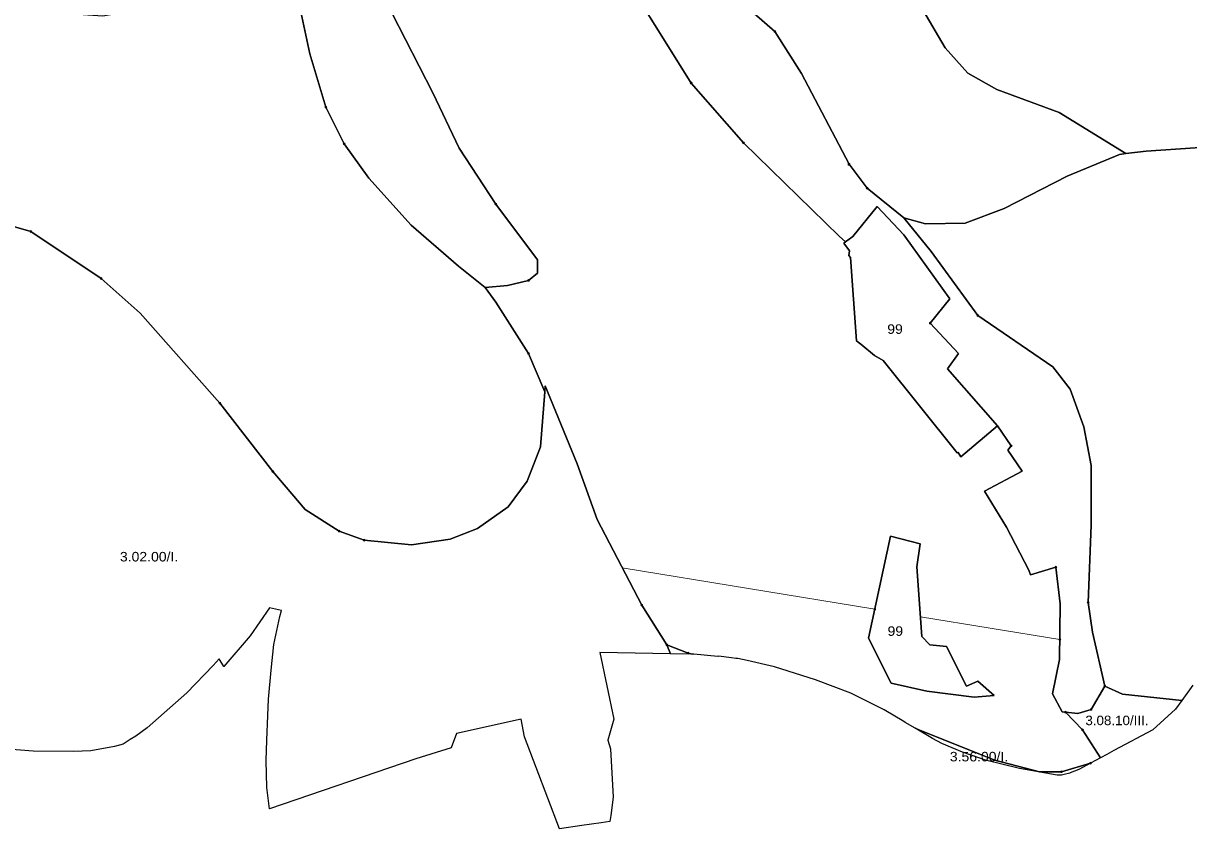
# Model space of a CAD drawing. Extents: x -650455 to -642254, y -1075222 to -1066610.
# Drawn here: x -646878 to -645652, y -1073104 to -1072257 of the extents above; entities that cross this region are included whole.
import ezdxf
from ezdxf.enums import TextEntityAlignment as Align

# ---------------------------------------------------------------- set-up
doc = ezdxf.new("R2010")
doc.units = 0
doc.header["$LTSCALE"] = 4
doc.header["$PDMODE"] = 32
doc.header["$PDSIZE"] = 2
for name, color, linetype, lineweight in [('1', 7, 'Continuous', 25), ('11', 7, 'Continuous', 13), ('13', 7, 'Continuous', 13), ('14', 7, 'Continuous', 13)]:
    doc.layers.add(name, color=color, linetype=linetype, lineweight=lineweight)
doc.layers.add('2', color=7, linetype='Continuous')

msp = doc.modelspace()

# ---------------------------------------------------------------- linework, layer by layer
at = {"layer": '1'}
for points in [[(-646550.686, -1071915.879), (-646559.5, -1071929.501), (-646506, -1071973.001), (-646478, -1071996), (-646472.545, -1072000), (-646448, -1072018.001), (-646420, -1072041), (-646408.5, -1072055.501), (-646389.5, -1072061.5), (-646345.4, -1072092.965), (-646345, -1072092.5), (-646296, -1072139.001), (-646248.5, -1072203), (-646175.5, -1072320), (-646120.5, -1072383.001), (-646020, -1072481), (-646013.29, -1072487.101)], [(-646908.5, -1072213.001), (-646859, -1072238.5), (-646830.5, -1072247), (-646794, -1072249.501), (-646766, -1072244.501), (-646725, -1072227.5), (-646651, -1072186), (-646624, -1072184.001), (-646611, -1072194), (-646595.5, -1072213.001), (-646588, -1072235.5), (-646576.5, -1072289.501), (-646559.5, -1072345.501), (-646540.5, -1072384), (-646514.5, -1072420.001), (-646470, -1072469.5), (-646420, -1072512.501), (-646392, -1072535), (-646381, -1072550.5), (-646346.5, -1072604.501), (-646329.469, -1072644.503), (-646334, -1072702.501), (-646348, -1072738.501), (-646368, -1072765.5)], [(-645894.5, -1072604.501), (-645924, -1072572.501), (-645903.5, -1072547), (-645952, -1072479.501), (-645979.711, -1072449.972), (-646005.6, -1072481.541), (-646013.29, -1072487.101), (-646020, -1072481), (-646120.5, -1072383.001), (-646175.5, -1072320), (-646248.5, -1072203)], [(-646504.5, -1072218), (-646447, -1072330.501), (-646419.5, -1072388.5), (-646381, -1072447.501), (-646337, -1072506), (-646337, -1072520.001), (-646346.5, -1072527.501), (-646368.5, -1072533.001), (-646392, -1072535), (-646420, -1072512.501), (-646470, -1072469.5), (-646514.5, -1072420.001), (-646540.5, -1072384), (-646559.5, -1072345.501), (-646576.5, -1072289.501), (-646588, -1072235.5)], [(-646044.852, -1072947.399), (-646087.992, -1072933.791), (-646116.558, -1072926.987), (-646126.295, -1072925.154), (-646128.552, -1072925.154), (-646133.068, -1072924.166), (-646146.615, -1072922.613), (-646147.305, -1072922.889), (-646172.567, -1072920.556), (-646174.324, -1072920.525), (-646178.5, -1072919.5), (-646201, -1072910.5), (-646227.5, -1072869.001), (-646274.5, -1072779.001), (-646295.5, -1072720.5), (-646329, -1072638.501), (-646329.469, -1072644.503), (-646346.5, -1072604.501), (-646381, -1072550.5), (-646392, -1072535), (-646368.5, -1072533.001), (-646346.5, -1072527.501), (-646337, -1072520.001), (-646337, -1072506), (-646381, -1072447.501), (-646419.5, -1072388.5), (-646447, -1072330.501), (-646504.5, -1072218)], [(-645932, -1072243), (-645908.5, -1072283), (-645884.5, -1072309.501), (-645854, -1072327), (-645788.5, -1072351.001), (-645718.5, -1072394.001), (-645725, -1072395.001), (-645780, -1072418), (-645846.5, -1072452.001), (-645887.5, -1072467.501), (-645929, -1072468.001), (-645951.948, -1072461.78), (-645990.5, -1072430.501), (-646009.5, -1072405.5), (-646059.5, -1072310.001), (-646087.5, -1072266.001), (-646128, -1072230)], [(-646128, -1072230), (-646087.5, -1072266.001), (-646059.5, -1072310.001), (-646009.5, -1072405.5), (-645990.5, -1072430.501), (-645951.948, -1072461.78), (-645923, -1072497.001), (-645874, -1072564.501), (-645795, -1072618.5), (-645777, -1072642.001), (-645762.5, -1072681.501), (-645755, -1072722.001), (-645755, -1072785), (-645758, -1072866), (-645753.5, -1072897.501), (-645740.5, -1072954.001), (-645755, -1072978.501), (-645769, -1072983), (-645781.991, -1072981.426), (-645785.5, -1072981.001), (-645795.5, -1072962.001), (-645788, -1072926.001), (-645787.5, -1072867.5), (-645792, -1072829.001), (-645818.5, -1072837.001), (-645820.5, -1072832.001), (-645844, -1072787.001), (-645867, -1072749), (-645827.5, -1072728), (-645842.5, -1072706.001), (-645839, -1072701.5), (-645853.5, -1072680.5), (-645906, -1072620.5), (-645894.5, -1072604.501)], [(-645788.5, -1072351.001), (-645854, -1072327), (-645884.5, -1072309.501), (-645908.5, -1072283), (-645932, -1072243)], [(-645594, -1072384.5), (-645697, -1072391.501), (-645718.5, -1072394.001), (-645788.5, -1072351.001)], [(-645648.03, -1072953.171), (-645659.633, -1072969.042), (-645722, -1072962.501), (-645740.5, -1072954.001), (-645753.5, -1072897.501), (-645758, -1072866), (-645755, -1072785), (-645755, -1072722.001), (-645762.5, -1072681.501), (-645777, -1072642.001), (-645795, -1072618.5), (-645874, -1072564.501), (-645923, -1072497.001), (-645951.948, -1072461.78), (-645929, -1072468.001), (-645887.5, -1072467.501), (-645846.5, -1072452.001), (-645780, -1072418), (-645725, -1072395.001), (-645718.5, -1072394.001), (-645697, -1072391.501), (-645594, -1072384.5)], [(-647197.5, -1072767.501), (-647163, -1072751.501), (-647115, -1072720.5), (-647095, -1072702.001), (-647061.5, -1072661.501), (-647051.5, -1072638.001), (-647024, -1072517.5), (-647011.5, -1072495), (-646994, -1072476.501), (-646978.5, -1072468.001), (-646949.5, -1072462), (-646909, -1072465), (-646870, -1072476.001), (-646796, -1072525.5), (-646755, -1072562), (-646671, -1072656.5), (-646615.5, -1072728.5), (-646581.5, -1072768.5), (-646545.5, -1072791.001), (-646519.5, -1072800.501)], [(-646368, -1072765.5), (-646400, -1072788.501), (-646429, -1072799.501), (-646469.5, -1072805.5), (-646519.5, -1072800.501), (-646545.5, -1072791.001), (-646581.5, -1072768.5), (-646615.5, -1072728.5), (-646671, -1072656.5), (-646755, -1072562), (-646796, -1072525.5), (-646870, -1072476.001), (-646909, -1072465)], [(-646013.29, -1072487.101), (-646015.05, -1072488.38), (-646008.85, -1072496.281), (-646009.51, -1072501.49), (-646008, -1072503.501), (-646001.5, -1072591), (-645999.77, -1072592.6), (-645996.89, -1072594.561), (-645982.84, -1072606.461), (-645973.45, -1072611.73), (-645895.91, -1072708.97), (-645894.58, -1072708.52), (-645891.891, -1072712.988), (-645853.5, -1072680.5), (-645839, -1072701.5), (-645842.5, -1072706.001), (-645827.5, -1072728), (-645867, -1072749), (-645844, -1072787.001), (-645820.5, -1072832.001), (-645818.5, -1072837.001), (-645792, -1072829.001), (-645787.5, -1072867.5), (-645788, -1072926.001), (-645795.5, -1072962.001), (-645785.5, -1072981.001), (-645781.991, -1072981.426), (-645764, -1073000), (-645744.901, -1073029.348), (-645755.631, -1073035.068), (-645786, -1073044), (-645809, -1073044), (-645856, -1073032), (-645936, -1073000), (-645940.001, -1072998.4), (-645950.335, -1072992.289), (-645951.835, -1072991.39), (-645972.369, -1072979.088), (-646007.736, -1072961.59), (-646044.852, -1072947.399)], [(-646519.5, -1072800.501), (-646469.5, -1072805.5), (-646429, -1072799.501), (-646400, -1072788.501), (-646368, -1072765.5), (-646348, -1072738.501), (-646334, -1072702.501), (-646329.469, -1072644.503), (-646329, -1072638.501), (-646295.5, -1072720.5), (-646274.5, -1072779.001), (-646227.5, -1072869.001), (-646201, -1072910.5), (-646197.074, -1072920.127), (-646271.37, -1072918.83), (-646256.628, -1072988.933), (-646263.043, -1073010.896), (-646260.47, -1073020.003), (-646257.448, -1073070.811), (-646260.097, -1073090), (-646261.077, -1073096.462), (-646270.039, -1073097.707), (-646290.434, -1073100.596), (-646313.957, -1073103.929), (-646350.634, -1073007.419), (-646354.291, -1072988.654), (-646422.376, -1073004.025), (-646427.959, -1073018.939), (-646464.927, -1073030.328), (-646619.029, -1073082.989), (-646621.552, -1073060.665), (-646622.395, -1073032.266), (-646621.615, -1073010.769), (-646620.678, -1072984.937), (-646620.049, -1072967.628), (-646617.063, -1072937.311), (-646614.405, -1072910.337), (-646608.196, -1072880.702), (-646606.34, -1072874.563), (-646618.894, -1072871.868)], [(-646618.894, -1072871.868), (-646639.36, -1072901.265), (-646667.031, -1072933.353), (-646671.949, -1072925.375), (-646678.069, -1072932.215), (-646705.921, -1072961.063), (-646747.701, -1072997.867), (-646759.354, -1073006.536), (-646765.283, -1073010.32), (-646772.712, -1073015.062), (-646781.949, -1073017.62), (-646806.959, -1073022.026), (-646825.149, -1073022.879), (-646867.497, -1073022.31), (-646894.212, -1073020.321)]]:
    msp.add_lwpolyline(points, dxfattribs=at)
for points in [[(-645853.5, -1072680.5), (-645891.891, -1072712.988), (-645894.58, -1072708.52), (-645895.91, -1072708.97), (-645973.45, -1072611.73), (-645982.84, -1072606.461), (-645996.89, -1072594.561), (-645999.77, -1072592.6), (-646001.5, -1072591), (-646008, -1072503.501), (-646009.51, -1072501.49), (-646008.85, -1072496.281), (-646015.05, -1072488.38), (-646013.29, -1072487.101), (-646005.6, -1072481.541), (-645979.711, -1072449.972), (-645952, -1072479.501), (-645903.5, -1072547), (-645924, -1072572.501), (-645894.5, -1072604.501), (-645906, -1072620.5)], [(-645907, -1072912.501), (-645886, -1072954.001), (-645874, -1072949.001), (-645857, -1072964), (-645878, -1072965.501), (-645927.5, -1072959.5), (-645965, -1072951), (-645989, -1072903.5), (-645966, -1072796.501), (-645934.5, -1072804.501), (-645938, -1072828.501), (-645933, -1072902), (-645924.5, -1072910.5)], [(-645907, -1072912.501), (-645924.5, -1072910.5), (-645933, -1072902), (-645938, -1072828.501), (-645934.5, -1072804.501), (-645966, -1072796.501), (-645989, -1072903.5), (-645965, -1072951), (-645927.5, -1072959.5), (-645878, -1072965.501), (-645857, -1072964), (-645874, -1072949.001), (-645886, -1072954.001)], [(-646178.5, -1072919.5), (-646174.324, -1072920.525), (-646197.074, -1072920.127), (-646201, -1072910.5)], [(-645666.315, -1072978.183), (-645690.151, -1073000.05), (-645730.916, -1073021.894), (-645738.336, -1073025.848), (-645744.901, -1073029.348), (-645764, -1073000), (-645781.991, -1072981.426), (-645769, -1072983), (-645755, -1072978.501), (-645740.5, -1072954.001), (-645722, -1072962.501), (-645659.633, -1072969.042)], [(-645856, -1073032), (-645809, -1073044), (-645786, -1073044), (-645755.631, -1073035.068), (-645767.974, -1073041.649), (-645777.06, -1073045.328), (-645777.396, -1073045.416), (-645783.246, -1073046.95), (-645786.145, -1073047.71), (-645788.257, -1073047.659), (-645790.688, -1073047.601), (-645830.275, -1073040.566), (-645865.968, -1073031.798), (-645889.98, -1073023.354), (-645911.829, -1073014.261), (-645921.78, -1073009.174), (-645940.001, -1072998.4), (-645936, -1073000)]]:
    msp.add_lwpolyline(points, close=True, dxfattribs=at)
at = {"layer": '11'}
for p, q in [((-646870, -1072476.001), (-646909, -1072465)), ((-646615.5, -1072728.5), (-646671, -1072656.5)), ((-646519.5, -1072800.501), (-646545.5, -1072791.001))]:
    msp.add_line(p, q, dxfattribs=at)
for points in [[(-646929.643, -1071786.538), (-646870.396, -1071861.944), (-646758.889, -1072000), (-646757.286, -1072001.985), (-646709, -1072113.5), (-646673, -1072147.501), (-646624, -1072184.001), (-646611, -1072194), (-646595.5, -1072213.001), (-646588, -1072235.5), (-646576.5, -1072289.501), (-646559.5, -1072345.501), (-646540.5, -1072384)], [(-646346.5, -1072527.501), (-646337, -1072520.001), (-646337, -1072506), (-646381, -1072447.501), (-646419.5, -1072388.5), (-646447, -1072330.501), (-646504.5, -1072218), (-646584, -1072105.5)], [(-646027.5, -1072126), (-646011, -1072139.501), (-645967.5, -1072184.501), (-645932, -1072243), (-645908.5, -1072283), (-645884.5, -1072309.501), (-645854, -1072327), (-645788.5, -1072351.001), (-645718.5, -1072394.001), (-645697, -1072391.501), (-645594, -1072384.5), (-645567.5, -1072387.001), (-645560, -1072390.001), (-645550.5, -1072338.001), (-645549, -1072189.5), (-645544.5, -1072153.5), (-645532, -1072135.501), (-645510.5, -1072118.5), (-645474.5, -1072111.501), (-645421, -1072113), (-645398, -1072117), (-645373.5, -1072126), (-645338.5, -1072147.001)], [(-646559.5, -1072345.501), (-646576.5, -1072289.501), (-646588, -1072235.5), (-646595.5, -1072213.001), (-646611, -1072194), (-646624, -1072184.001), (-646651, -1072186), (-646725, -1072227.5)], [(-646346.5, -1072604.501), (-646381, -1072550.5), (-646392, -1072535), (-646420, -1072512.501), (-646470, -1072469.5), (-646514.5, -1072420.001), (-646540.5, -1072384), (-646559.5, -1072345.501)], [(-646540.5, -1072384), (-646514.5, -1072420.001), (-646470, -1072469.5), (-646420, -1072512.501), (-646392, -1072535), (-646368.5, -1072533.001), (-646346.5, -1072527.501)], [(-647083, -1072482.5), (-647052.5, -1072495.501), (-647024, -1072517.5), (-647011.5, -1072495), (-646994, -1072476.501), (-646978.5, -1072468.001), (-646949.5, -1072462), (-646909, -1072465), (-646870, -1072476.001), (-646796, -1072525.5)], [(-646671, -1072656.5), (-646755, -1072562), (-646796, -1072525.5), (-646870, -1072476.001)], [(-646796, -1072525.5), (-646755, -1072562), (-646671, -1072656.5), (-646615.5, -1072728.5), (-646581.5, -1072768.5), (-646545.5, -1072791.001), (-646519.5, -1072800.501), (-646469.5, -1072805.5), (-646429, -1072799.501), (-646400, -1072788.501), (-646368, -1072765.5), (-646348, -1072738.501), (-646334, -1072702.501), (-646329.469, -1072644.503), (-646346.5, -1072604.501)], [(-646227.5, -1072869.001), (-646274.5, -1072779.001), (-646295.5, -1072720.5), (-646329, -1072638.501), (-646329.469, -1072644.503), (-646334, -1072702.501), (-646348, -1072738.501), (-646368, -1072765.5), (-646400, -1072788.501), (-646429, -1072799.501), (-646469.5, -1072805.5), (-646519.5, -1072800.501)], [(-646545.5, -1072791.001), (-646581.5, -1072768.5), (-646615.5, -1072728.5)], [(-646894.212, -1073020.321), (-646867.497, -1073022.31), (-646825.149, -1073022.879), (-646806.959, -1073022.026), (-646781.949, -1073017.62), (-646772.712, -1073015.062), (-646765.283, -1073010.32), (-646759.354, -1073006.536), (-646747.701, -1072997.867), (-646705.921, -1072961.063), (-646678.069, -1072932.215), (-646671.949, -1072925.375), (-646667.031, -1072933.353), (-646639.36, -1072901.265), (-646618.894, -1072871.868), (-646606.34, -1072874.563), (-646608.196, -1072880.702), (-646614.405, -1072910.337), (-646617.063, -1072937.311), (-646620.049, -1072967.628), (-646620.678, -1072984.937), (-646621.615, -1073010.769), (-646622.395, -1073032.266), (-646621.552, -1073060.665), (-646619.029, -1073082.989), (-646464.927, -1073030.328), (-646427.959, -1073018.939), (-646422.376, -1073004.025), (-646354.291, -1072988.654)], [(-646354.291, -1072988.654), (-646350.634, -1073007.419), (-646313.957, -1073103.929), (-646290.434, -1073100.596), (-646270.039, -1073097.707), (-646261.077, -1073096.462), (-646260.097, -1073090), (-646257.448, -1073070.811), (-646260.47, -1073020.003), (-646263.043, -1073010.896), (-646256.628, -1072988.933), (-646271.37, -1072918.83), (-646197.074, -1072920.127), (-646201, -1072910.5), (-646227.5, -1072869.001)], [(-645786, -1073044), (-645809, -1073044), (-645856, -1073032), (-645936, -1073000), (-645940.001, -1072998.4), (-645921.78, -1073009.174), (-645911.829, -1073014.261), (-645889.98, -1073023.354), (-645865.968, -1073031.798)], [(-645865.968, -1073031.798), (-645830.275, -1073040.566), (-645790.688, -1073047.601), (-645788.257, -1073047.659), (-645786.145, -1073047.71), (-645783.246, -1073046.95), (-645777.396, -1073045.416), (-645777.06, -1073045.328), (-645767.974, -1073041.649), (-645755.631, -1073035.068), (-645786, -1073044)]]:
    msp.add_lwpolyline(points, dxfattribs=at)
for p in [(-646559.5, -1072345.501), (-646540.5, -1072384), (-646870, -1072476.001), (-646796, -1072525.5), (-646346.5, -1072527.501), (-646346.5, -1072604.501), (-646671, -1072656.5), (-646615.5, -1072728.5), (-646545.5, -1072791.001), (-646519.5, -1072800.501), (-646227.5, -1072869.001), (-645786, -1073044)]:
    msp.add_point(p, dxfattribs=at)
at = {"layer": '13'}
msp.add_line((-645874, -1072564.501), (-645795, -1072618.5), dxfattribs=at)
for points in [[(-646128, -1072230), (-646087.5, -1072266.001)], [(-646009.5, -1072405.5), (-645990.5, -1072430.501), (-645951.948, -1072461.78), (-645929, -1072468.001), (-645887.5, -1072467.501), (-645846.5, -1072452.001), (-645780, -1072418), (-645725, -1072395.001), (-645718.5, -1072394.001), (-645788.5, -1072351.001), (-645854, -1072327), (-645884.5, -1072309.501), (-645908.5, -1072283), (-645932, -1072243)], [(-646087.5, -1072266.001), (-646059.5, -1072310.001), (-646009.5, -1072405.5)], [(-645594, -1072384.5), (-645697, -1072391.501), (-645718.5, -1072394.001), (-645725, -1072395.001), (-645780, -1072418), (-645846.5, -1072452.001), (-645887.5, -1072467.501), (-645929, -1072468.001), (-645951.948, -1072461.78), (-645923, -1072497.001), (-645874, -1072564.501)], [(-645795, -1072618.5), (-645777, -1072642.001), (-645762.5, -1072681.501), (-645755, -1072722.001), (-645755, -1072785), (-645758, -1072866), (-645753.5, -1072897.501), (-645740.5, -1072954.001)], [(-645740.5, -1072954.001), (-645722, -1072962.501), (-645659.633, -1072969.042), (-645648.03, -1072953.171)]]:
    msp.add_lwpolyline(points, dxfattribs=at)
msp.add_lwpolyline([(-645744.901, -1073029.348), (-645738.336, -1073025.848), (-645730.916, -1073021.894), (-645690.151, -1073000.05), (-645666.315, -1072978.183), (-645659.633, -1072969.042), (-645722, -1072962.501), (-645740.5, -1072954.001), (-645755, -1072978.501), (-645769, -1072983), (-645781.991, -1072981.426), (-645764, -1073000)], close=True, dxfattribs=at)
for p in [(-646009.5, -1072405.5), (-645874, -1072564.501), (-645740.5, -1072954.001)]:
    msp.add_point(p, dxfattribs=at)
at = {"layer": '14'}
for p, q in [((-646120.5, -1072383.001), (-646175.5, -1072320)), ((-646201, -1072910.5), (-646178.5, -1072919.5)), ((-645755, -1072978.501), (-645740.5, -1072954.001)), ((-645764, -1073000), (-645781.991, -1072981.426))]:
    msp.add_line(p, q, dxfattribs=at)
for points in [[(-646577.5, -1072041), (-646604, -1072062.501), (-646584, -1072105.5), (-646504.5, -1072218), (-646447, -1072330.501), (-646419.5, -1072388.5), (-646381, -1072447.501)], [(-646087.5, -1072266.001), (-646128, -1072230), (-646179, -1072180.501), (-646227, -1072108.5)], [(-646175.5, -1072320), (-646248.5, -1072203), (-646296, -1072139.001)], [(-646248.5, -1072203), (-646175.5, -1072320), (-646120.5, -1072383.001), (-646020, -1072481), (-646013.29, -1072487.101), (-646005.6, -1072481.541), (-645979.711, -1072449.972), (-645952, -1072479.501), (-645903.5, -1072547), (-645924, -1072572.501)], [(-645990.5, -1072430.501), (-646009.5, -1072405.5), (-646059.5, -1072310.001), (-646087.5, -1072266.001)], [(-645787.821, -1072905.039), (-645787.5, -1072867.5), (-645792, -1072829.001), (-645818.5, -1072837.001), (-645820.5, -1072832.001), (-645844, -1072787.001), (-645867, -1072749), (-645827.5, -1072728), (-645842.5, -1072706.001), (-645839, -1072701.5), (-645853.5, -1072680.5), (-645891.891, -1072712.988), (-645894.58, -1072708.52), (-645895.91, -1072708.97), (-645973.45, -1072611.73), (-645982.84, -1072606.461), (-645996.89, -1072594.561), (-645999.77, -1072592.6), (-646001.5, -1072591), (-646008, -1072503.501), (-646009.51, -1072501.49), (-646008.85, -1072496.281), (-646015.05, -1072488.38), (-646013.29, -1072487.101), (-646020, -1072481), (-646120.5, -1072383.001)], [(-645874, -1072564.501), (-645923, -1072497.001), (-645951.948, -1072461.78), (-645990.5, -1072430.501)], [(-646381, -1072447.501), (-646337, -1072506), (-646337, -1072520.001), (-646346.5, -1072527.501), (-646368.5, -1072533.001), (-646392, -1072535), (-646381, -1072550.5), (-646346.5, -1072604.501), (-646329.469, -1072644.503), (-646329, -1072638.501), (-646295.5, -1072720.5), (-646274.5, -1072779.001), (-646248.012, -1072829.723), (-645982.483, -1072873.18)], [(-645758, -1072866), (-645755, -1072785), (-645755, -1072722.001), (-645762.5, -1072681.501), (-645777, -1072642.001), (-645795, -1072618.5), (-645874, -1072564.501)], [(-645924, -1072572.501), (-645894.5, -1072604.501), (-645906, -1072620.5), (-645853.5, -1072680.5), (-645839, -1072701.5)], [(-645839, -1072701.5), (-645842.5, -1072706.001), (-645827.5, -1072728), (-645867, -1072749), (-645844, -1072787.001), (-645820.5, -1072832.001), (-645818.5, -1072837.001), (-645792, -1072829.001)], [(-645982.483, -1072873.18), (-645966, -1072796.501), (-645934.5, -1072804.501), (-645938, -1072828.501), (-645934.426, -1072881.045), (-645787.821, -1072905.039)], [(-645781.991, -1072981.426), (-645785.5, -1072981.001), (-645795.5, -1072962.001), (-645788, -1072926.001), (-645787.821, -1072905.039), (-645934.426, -1072881.045), (-645933, -1072902), (-645924.5, -1072910.5), (-645907, -1072912.501), (-645886, -1072954.001), (-645874, -1072949.001), (-645857, -1072964), (-645878, -1072965.501), (-645927.5, -1072959.5), (-645965, -1072951), (-645989, -1072903.5), (-645982.483, -1072873.18), (-646248.012, -1072829.723), (-646227.5, -1072869.001), (-646201, -1072910.5)], [(-645792, -1072829.001), (-645787.5, -1072867.5), (-645787.821, -1072905.039), (-645788, -1072926.001), (-645795.5, -1072962.001), (-645785.5, -1072981.001), (-645781.991, -1072981.426), (-645769, -1072983), (-645755, -1072978.501)], [(-645740.5, -1072954.001), (-645753.5, -1072897.501), (-645758, -1072866)], [(-646178.5, -1072919.5), (-646174.324, -1072920.525), (-646172.567, -1072920.556), (-646147.305, -1072922.889), (-646146.615, -1072922.613), (-646133.068, -1072924.166), (-646128.552, -1072925.154), (-646126.295, -1072925.154), (-646116.558, -1072926.987), (-646087.992, -1072933.791), (-646044.852, -1072947.399), (-646007.736, -1072961.59), (-645972.369, -1072979.088), (-645951.835, -1072991.39), (-645950.335, -1072992.289), (-645940.001, -1072998.4), (-645936, -1073000), (-645856, -1073032), (-645809, -1073044), (-645786, -1073044), (-645755.631, -1073035.068)], [(-645755.631, -1073035.068), (-645744.901, -1073029.348), (-645764, -1073000)]]:
    msp.add_lwpolyline(points, dxfattribs=at)
for p in [(-646087.5, -1072266.001), (-646175.5, -1072320), (-646120.5, -1072383.001), (-645990.5, -1072430.501), (-646381, -1072447.501), (-645924, -1072572.501), (-645874, -1072564.501), (-645839, -1072701.5), (-645792, -1072829.001), (-645758, -1072866), (-645982.483, -1072873.18), (-646201, -1072910.5), (-645787.821, -1072905.039), (-646178.5, -1072919.5), (-645740.5, -1072954.001), (-645781.991, -1072981.426), (-645755, -1072978.501), (-645764, -1073000), (-645755.631, -1073035.068)]:
    msp.add_point(p, dxfattribs=at)

# ---------------------------------------------------------------- texts
at = {"layer": '2'}
for s, width, p in [('99', 1.1, (-645961.093, -1072583.68)), ('3.02.00/I.', 1.1, (-646745.524, -1072822.982)), ('99', 1.1, (-645960.785, -1072901.18)), ('3.08.10/III.', 1.05, (-645727.731, -1072995.105)), ('3.56.00/I.', 1.1, (-645872.789, -1073033.186))]:
    msp.add_text(s, height=10, dxfattribs=dict(at, width=width)).set_placement(p, align=Align.CENTER)

doc.saveas('drawing.dxf')
